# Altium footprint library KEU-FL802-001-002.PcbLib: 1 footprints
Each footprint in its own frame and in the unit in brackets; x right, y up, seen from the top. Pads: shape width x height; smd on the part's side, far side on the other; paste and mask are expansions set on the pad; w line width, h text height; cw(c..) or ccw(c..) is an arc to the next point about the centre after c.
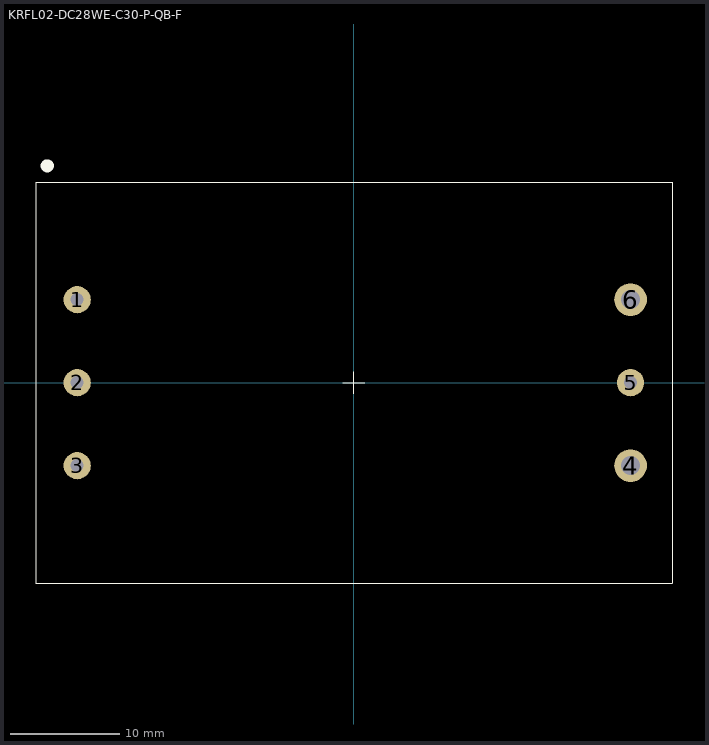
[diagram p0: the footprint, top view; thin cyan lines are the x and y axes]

## KRFL02-DC28WE-C30-P-QB-F [mm] "KRFL02-DC28WE-C30-P-QB-F"
height 12.7
pads (6):
  round 2.5 hole 1.2: 1(-25.4,7.62) 2(-25.4,0) 3(-25.4,-7.62) 5(25.4,0)
  round 3 hole 1.75: 4(25.4,-7.62) 6(25.4,7.62)
Top Overlay:
  circle w1: c-28.15,19.905 r0.1
  lines w0.1: -1,0 0,0 ; 0,-1 0,0 ; 0,1 0,0 ; 1,0 0,0 ; -29.2,-18.419 -29.2,18.402 29.222,18.402 29.222,-18.419 -29.2,-18.419
Bottom Overlay:
  circle w1: c-28.15,16.895 r0.1
  text "+VIN" at -28.55,6.396 h0.7
  text "CM_IN" at -28.492,-1.574 h0.7
  text "-VIN" at -28.55,-8.849 h0.7
  text "+VOUT" at 27.85,6.009 h0.7
  text "CM_OUT" at 27.908,-1.99 h0.7
  text "-VOUT" at 27.85,-9.291 h0.7
3D body "KRFL02-F.STEP": height 12.71, standoff -4.29, extent -29.2,-28 29.2,28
